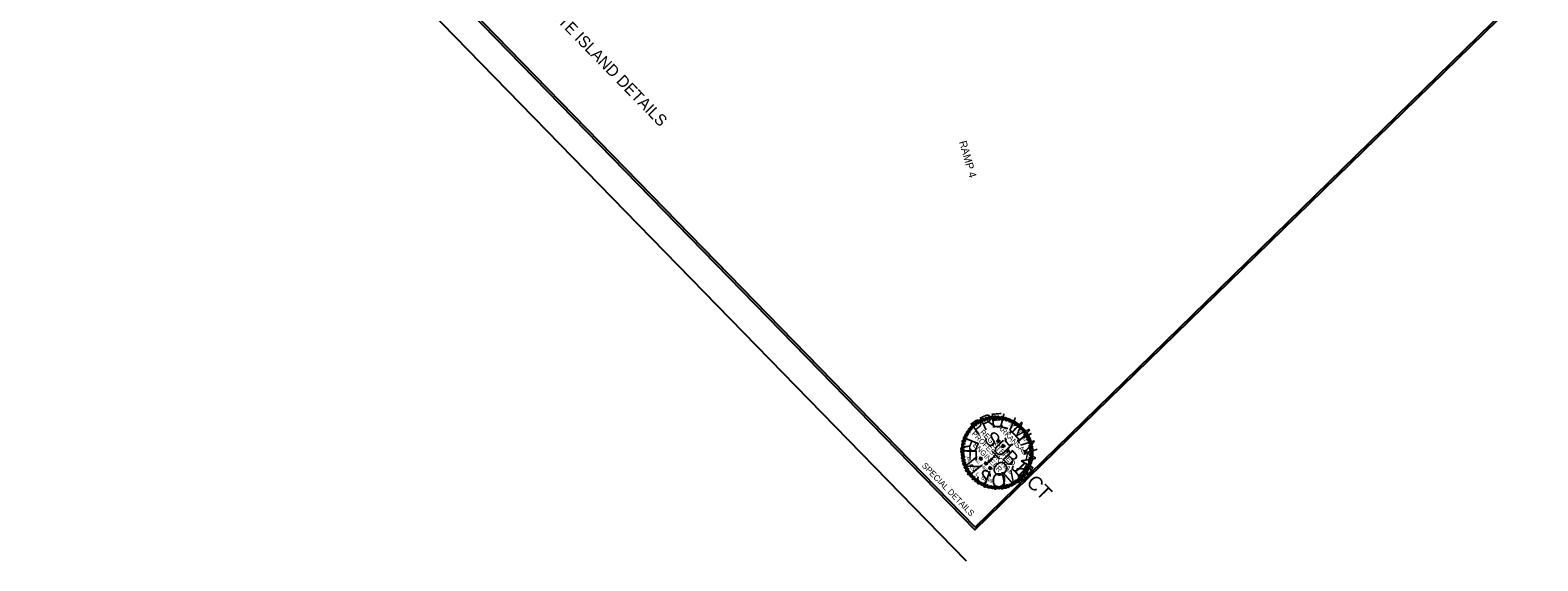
# Model space of a CAD drawing. Extents: x 1309825 to 1312816, y 238906 to 242017.
# Drawn here: x 1309825 to 1310815, y 241003 to 241351 of the extents above; entities that cross this region are included whole.
import ezdxf

# ---------------------------------------------------------------- set-up
doc = ezdxf.new("R2010")
doc.units = 0
for name, color, linetype in [('R_Annotation', 7, 'Continuous'), ('R_Border', 7, 'Continuous'), ('R_Border Notes', 7, 'Continuous'), ('R_Border PE', 7, 'Continuous'), ('R_Border Prem', 7, 'Continuous'), ('R_No Plot', 7, 'Continuous')]:
    doc.layers.add(name, color=color, linetype=linetype)

msp = doc.modelspace()

# ---------------------------------------------------------------- linework, layer by layer
at = {"layer": 'R_Border'}
for p, q in [((1309824.66, 241632.77), (1310439.19, 241002.82)), ((1310445.23, 241024.81), (1309893.27, 241590.69)), ((1310445.23, 241024.81), (1310812.92, 241383.47))]:
    msp.add_line(p, q, dxfattribs=at)
at = {"layer": 'R_Border PE'}
for points in [[(1310468.07, 241086.48), (1310468.87, 241088), (1310474.4, 241082), (1310473.19, 241081.67), (1310474.01, 241080.72), (1310473.85, 241080.67)], [(1310469.8, 241078.88), (1310468.81, 241078.86), (1310468.11, 241077.96), (1310464.81, 241081.56), (1310465.56, 241082.29), (1310464.95, 241082.92), (1310465.42, 241083.37)]]:
    msp.add_lwpolyline(points, dxfattribs=at)
for points in [[(1310461.16, 241082.12), (1310460.8, 241081.45), (1310461.3, 241080.93), (1310460.62, 241081.1), (1310460.24, 241080.41), (1310460.16, 241081.14), (1310459.42, 241081.25), (1310460.11, 241081.62), (1310459.96, 241082.31), (1310460.48, 241081.77)], [(1310464.41, 241078.89), (1310464.1, 241078.28), (1310464.57, 241077.79), (1310463.88, 241077.86), (1310463.55, 241077.22), (1310463.4, 241077.92), (1310462.72, 241078.08), (1310463.36, 241078.39), (1310463.28, 241079.12), (1310463.78, 241078.6)], [(1310449.72, 241070.64), (1310449.32, 241069.98), (1310449.85, 241069.44), (1310449.18, 241069.62), (1310448.8, 241068.94), (1310448.72, 241069.67), (1310447.98, 241069.78), (1310448.67, 241070.14), (1310448.5, 241070.82), (1310449.02, 241070.28)], [(1310452.97, 241067.42), (1310452.64, 241066.79), (1310453.11, 241066.3), (1310452.39, 241066.44), (1310452.12, 241065.75), (1310451.96, 241066.44), (1310451.28, 241066.61), (1310451.92, 241066.92), (1310451.82, 241067.63), (1310452.33, 241067.11)], [(1310467.3, 241075.82), (1310466.94, 241075.15), (1310467.45, 241074.63), (1310466.78, 241074.78), (1310466.4, 241074.09), (1310466.3, 241074.84), (1310465.56, 241074.95), (1310466.25, 241075.32), (1310466.1, 241076.01), (1310466.63, 241075.47)], [(1310455.86, 241064.34), (1310455.48, 241063.66), (1310455.99, 241063.14), (1310455.34, 241063.31), (1310454.94, 241062.64), (1310454.86, 241063.37), (1310454.12, 241063.48), (1310454.81, 241063.84), (1310454.65, 241064.52), (1310455.17, 241063.98)]]:
    msp.add_lwpolyline(points, close=True, dxfattribs=at)
for centre, major_axis, ratio in [((1310453.5, 241096.11), (-0.71, -1.24), 0.322879), ((1310455.56, 241096.58), (-1.02, -0.99), 0.322879), ((1310457.47, 241096.78), (-1.02, -0.99), 0.322879), ((1310459.46, 241096.92), (-1.25, -0.68), 0.391724), ((1310461.97, 241096.6), (-1.25, -0.68), 0.394697), ((1310440.06, 241086.42), (-0.06, -1.42), 0.322879), ((1310441.22, 241088.2), (-0.06, -1.42), 0.322879), ((1310442.53, 241089.97), (-0.33, -1.39), 0.322879), ((1310444.12, 241091.35), (-0.33, -1.39), 0.322879), ((1310445.65, 241092.67), (-0.33, -1.39), 0.322879), ((1310447.62, 241094.02), (-0.71, -1.24), 0.322879), ((1310449.61, 241094.87), (-0.71, -1.24), 0.322879), ((1310451.65, 241095.62), (-0.71, -1.24), 0.322879), ((1310464.16, 241095.98), (-1.25, -0.68), 0.375751), ((1310466.5, 241095.33), (-1.35, -0.46), 0.329518), ((1310468.77, 241094.42), (-1.42, -0.13), 0.329518), ((1310470.72, 241093.47), (-1.42, -0.12), 0.329518), ((1310472.57, 241092.22), (-1.55, 0.09), 0.348728), ((1310474.12, 241090.82), (-1.22, 0.16), 0.44237), ((1310475.96, 241089.23), (-1.17, 0.32), 0.475469), ((1310477.32, 241087.52), (-1.17, 0.32), 0.475469), ((1310437.14, 241078.19), (0.45, -1.35), 0.322879), ((1310437.52, 241080.41), (0.45, -1.35), 0.322879), ((1310438.16, 241082.51), (0.23, -1.41), 0.322879), ((1310438.92, 241084.42), (0.08, -1.42), 0.322879), ((1310478.47, 241085.81), (-1.17, 0.32), 0.475469), ((1310479.51, 241084.04), (-1.07, 0.57), 0.475469), ((1310480.3, 241082.21), (-0.996, 0.7), 0.475469), ((1310481.03, 241080.18), (-0.922, 0.795), 0.475469), ((1310481.71, 241077.94), (-0.922, 0.795), 0.475469), ((1310436.78, 241073.75), (0.76, -1.21), 0.322879), ((1310436.83, 241075.78), (0.76, -1.21), 0.322879), ((1310437.11, 241071.61), (0.76, -1.21), 0.322879), ((1310437.37, 241069.5), (1.08, -0.93), 0.322879), ((1310437.84, 241067.62), (1.08, -0.93), 0.322879), ((1310481.17, 241067.64), (-0.38, 1.38), 0.40589), ((1310481.71, 241069.66), (-0.64, 1.23), 0.418512), ((1310481.95, 241075.86), (-0.83, 0.891), 0.475469), ((1310481.98, 241073.93), (-0.76, 1.03), 0.451028), ((1310481.95, 241071.7), (-0.69, 1.13), 0.436264), ((1310438.42, 241065.68), (1.08, -0.93), 0.40589), ((1310439.37, 241063.47), (1.23, -0.72), 0.40589), ((1310440.35, 241061.52), (1.23, -0.72), 0.40589), ((1310441.72, 241059.63), (1.38, -0.37), 0.40589), ((1310443.3, 241057.97), (1.38, -0.37), 0.40589), ((1310474.93, 241056.85), (0.41, 1.37), 0.40589), ((1310476.39, 241058.32), (0.19, 1.41), 0.40589), ((1310477.73, 241059.93), (-0.01, 1.43), 0.40589), ((1310478.8, 241061.57), (-0.08, 1.42), 0.40589), ((1310479.74, 241063.41), (-0.08, 1.42), 0.40589), ((1310480.63, 241065.36), (-0.23, 1.41), 0.40589), ((1310444.7, 241056.5), (1.4, -0.25), 0.40589), ((1310446.5, 241055.09), (1.42, -0.14), 0.40589), ((1310448.22, 241053.81), (1.43, -0.04), 0.40589), ((1310450.4, 241052.92), (1.41, 0.19), 0.40589), ((1310452.36, 241051.9), (1.35, 0.47), 0.40589), ((1310454.68, 241051.35), (1.33, 0.51), 0.40589), ((1310457.11, 241051.15), (1.23, 0.72), 0.40589), ((1310459.18, 241050.76), (1.17, 0.82), 0.40589), ((1310461.41, 241051), (1.17, 0.82), 0.40589), ((1310463.5, 241051.07), (1.07, 0.95), 0.40589), ((1310465.65, 241051.59), (0.96, 1.05), 0.40589), ((1310467.52, 241052.1), (0.96, 1.05), 0.40589), ((1310469.55, 241053.11), (0.83, 1.16), 0.40589), ((1310471.56, 241054.44), (0.73, 1.23), 0.40589), ((1310473.32, 241055.45), (0.53, 1.32), 0.40589)]:
    msp.add_ellipse(centre, major_axis=major_axis, ratio=ratio, dxfattribs=at)
at = {"layer": 'R_Border Prem'}
msp.add_circle((1310459.66, 241074.01), 23.15, dxfattribs=at)
at = {"layer": 'R_No Plot'}
msp.add_lwpolyline([(1309891.65, 241590.49), (1310445.01, 241023.21), (1310814.59, 241383.69), (1310261.18, 241950.99)], close=True, dxfattribs=at)

# ---------------------------------------------------------------- texts
at = {"layer": 'R_Annotation'}
for s, height, rotation, p in [('CONCRETE ISLAND DETAILS', 7.5272, 314.28649, (1310140.28, 241387.7)), ('RAMP 4', 5, 286.04496, (1310434.52, 241277.67))]:
    msp.add_text(s, height=height, rotation=rotation, dxfattribs=at).set_placement(p)
at = {"layer": 'R_Border Notes'}
msp.add_text('SPECIAL DETAILS', height=4, rotation=314.28668, dxfattribs=at).set_placement((1310409.81, 241064.91))
at = {"layer": 'R_Border PE'}
for s, height, rotation, p in [('PROFESSIONAL', 3.4534, 314.28831, (1310442.52, 241085.97)), ('REGISTERED', 3.453, 314.28831, (1310448.08, 241086.96)), ('ARKANSAS', 3.453, 314.28831, (1310459.53, 241090.27)), ('S', 1.73, 333.86966, (1310467.23, 241091.57)), ('T', 1.73, 329.24975, (1310468.95, 241090.66)), ('A', 1.73, 320.00993, (1310470.57, 241089.65)), ('T', 1.73, 315.39002, (1310472.13, 241088.27)), ('E', 1.73, 310.77011, (1310473.52, 241086.84)), ('ENGINEER', 3.453, 314.28831, (1310443.38, 241078.43)), ('O', 1.73, 296.91038, (1310475.83, 241083.72)), ('F', 1.73, 292.29047, (1310476.75, 241081.92)), ('J', 2.4, 276.705, (1310439.55, 241071.83)), ('A', 2.4, 282.3054, (1310439.83, 241069.83)), ('M', 2.4, 287.9058, (1310440.42, 241067.51)), ('No. 9808', 1.973, 314.28831, (1310444.8, 241068.71)), ('E', 2.4, 299.10661, (1310441.34, 241065.09)), ('S', 2.4, 304.70701, (1310442.38, 241063.17)), ('L', 2.4, 315.90781, (1310445.23, 241059.56)), ('.', 2.4, 321.50821, (1310446.89, 241058.07)), ('B', 2.4, 332.70902, (1310448.85, 241056.6)), ('A', 2.4, 338.30942, (1310450.87, 241055.49)), ('R', 2.4, 343.90982, (1310453.13, 241054.62)), ('R', 2.4, 349.51023, (1310455.36, 241054.04))]:
    msp.add_text(s, height=height, rotation=rotation, dxfattribs=at).set_placement(p)
at = {"layer": 'R_Border Prem'}
for s, rotation, p in [('R', 24.58943, (1310450.87, 241087.97)), ('E', 5.27319, (1310455.67, 241090.07)), ('L', 345.95696, (1310460.28, 241090.72)), ('P', 36.89719, (1310446.55, 241084.63)), ('SUBJECT', 314.28831, (1310450.15, 241082.41)), ('I', 336.29884, (1310466.23, 241088.98)), ('M', 316.9826, (1310468.38, 241088.25)), ('R', 248.05218, (1310439.55, 241084.54)), ('I', 297.66637, (1310473.08, 241083.65)), ('N', 288.00825, (1310474.82, 241080.25)), ('E', 268.61449, (1310437.12, 241076.58)), ('V', 289.1768, (1310437.52, 241068.9)), ('TO', 314.28831, (1310449.71, 241068.86)), ('R', 239.71766, (1310476.14, 241069.8)), ('A', 259.03389, (1310476.69, 241075.96)), ('I', 309.73912, (1310441.13, 241060.97)), ('S', 320.02027, (1310444.78, 241057.02)), ('I', 340.58259, (1310450.05, 241053.44)), ('O', 350.86374, (1310455.2, 241051.85)), ('N', 11.42606, (1310463.13, 241051.67)), ('Y', 220.40142, (1310474.06, 241064.77))]:
    msp.add_text(s, height=9.31, rotation=rotation, dxfattribs=at).set_placement(p)

doc.saveas('drawing.dxf')
